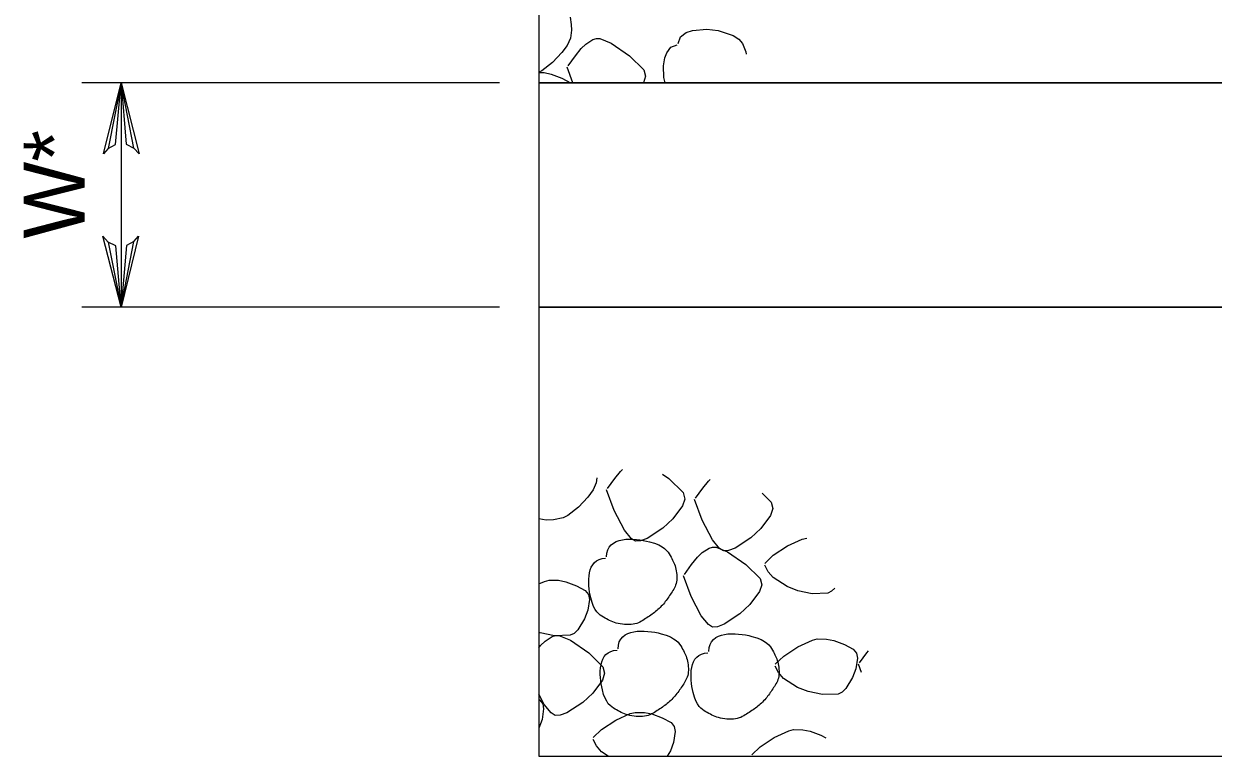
# Model space of a CAD drawing. Extents: x 636462 to 638208, y 299350 to 300538.
# Drawn here: x 637673.2 to 637731.8, y 299723.9 to 299760 of the extents above; entities that cross this region are included whole.
import ezdxf

# ---------------------------------------------------------------- set-up
doc = ezdxf.new("R2010")
doc.units = 0
doc.layers.add('Default', color=7, linetype='Continuous')

msp = doc.modelspace()

# ---------------------------------------------------------------- linework, layer by layer
at = {"layer": 'Default'}
for p, q in [((637700.101, 299760.333), (637700.163, 299759.98)), ((637700.174, 299759.704), (637700.119, 299759.303)), ((637700.163, 299759.98), (637700.174, 299759.704)), ((637705.545, 299759.377), (637705.813, 299759.58)), ((637705.813, 299759.58), (637706.137, 299759.688)), ((637706.137, 299759.688), (637706.833, 299759.743)), ((637706.833, 299759.743), (637707.388, 299759.679)), ((637707.388, 299759.679), (637708.132, 299759.437)), ((637699.967, 299758.951), (637699.704, 299758.594)), ((637700.119, 299759.303), (637699.967, 299758.951)), ((637700.656, 299758.79), (637700.881, 299759.015)), ((637700.881, 299759.015), (637701.227, 299759.243)), ((637701.227, 299759.243), (637701.397, 299759.292)), ((637701.397, 299759.292), (637701.565, 299759.285)), ((637701.565, 299759.285), (637702.13, 299759.057)), ((637702.13, 299759.057), (637703.035, 299758.439)), ((637705.073, 299758.866), (637705.38, 299758.974)), ((637705.423, 299759.041), (637705.545, 299759.377)), ((637708.132, 299759.437), (637708.411, 299759.255)), ((637708.411, 299759.255), (637708.595, 299759.041)), ((637708.595, 299759.041), (637708.752, 299758.638)), ((637699.704, 299758.594), (637699.242, 299758.108)), ((637700.004, 299757.944), (637700.363, 299758.435)), ((637700.363, 299758.435), (637700.656, 299758.79)), ((637703.035, 299758.439), (637703.733, 299757.744)), ((637704.707, 299757.94), (637704.772, 299758.336)), ((637704.772, 299758.336), (637704.864, 299758.589)), ((637704.864, 299758.589), (637705.073, 299758.866)), ((637708.752, 299758.638), (637708.77, 299758.522)), ((637699.242, 299758.108), (637698.716, 299757.7)), ((637700.246, 299757.106), (637699.958, 299757.877)), ((637703.733, 299757.744), (637703.813, 299757.428)), ((637704.721, 299757.362), (637704.707, 299757.94)), ((637698.716, 299757.7), (637698.562, 299757.622)), ((637698.562, 299757.608), (637698.82, 299757.606)), ((637698.82, 299757.606), (637699.179, 299757.532)), ((637699.179, 299757.532), (637699.7, 299757.341)), ((637699.7, 299757.341), (637700.131, 299757.106)), ((637703.813, 299757.428), (637703.712, 299757.106)), ((637704.778, 299757.106), (637704.721, 299757.362)), ((637696.627, 299757.106), (637676.053, 299757.106)), ((637696.627, 299746.05), (637676.053, 299746.05)), ((637702.3, 299737.611), (637702.593, 299737.966)), ((637702.593, 299737.966), (637702.683, 299738.056)), ((637704.649, 299737.837), (637704.97, 299737.616)), ((637701.388, 299737.402), (637701.236, 299737.052)), ((637701.423, 299737.657), (637701.388, 299737.402)), ((637701.939, 299737.121), (637702.3, 299737.611)), ((637704.97, 299737.616), (637705.668, 299736.92)), ((637706.635, 299737.139), (637706.927, 299737.492)), ((637706.927, 299737.492), (637707.006, 299737.572)), ((637700.974, 299736.692), (637700.511, 299736.206)), ((637701.236, 299737.052), (637700.974, 299736.692)), ((637702.275, 299736.034), (637701.895, 299737.054)), ((637705.668, 299736.92), (637705.75, 299736.605)), ((637706.273, 299736.649), (637706.635, 299737.139)), ((637709.555, 299736.89), (637710.002, 299736.448)), ((637700.511, 299736.206), (637699.985, 299735.801)), ((637705.644, 299736.271), (637705.17, 299735.631)), ((637705.75, 299736.605), (637705.644, 299736.271)), ((637706.61, 299735.561), (637706.229, 299736.582)), ((637710.085, 299736.133), (637709.979, 299735.799)), ((637710.002, 299736.448), (637710.085, 299736.133)), ((637698.924, 299735.573), (637698.562, 299735.633)), ((637699.294, 299735.578), (637698.924, 299735.573)), ((637699.755, 299735.684), (637699.294, 299735.578)), ((637699.985, 299735.801), (637699.755, 299735.684)), ((637702.775, 299735.073), (637702.275, 299736.034)), ((637705.17, 299735.631), (637704.675, 299735.175)), ((637707.109, 299734.601), (637706.61, 299735.561)), ((637709.979, 299735.799), (637709.505, 299735.158)), ((637703.129, 299734.647), (637702.775, 299735.073)), ((637704.675, 299735.175), (637703.896, 299734.663)), ((637709.505, 299735.158), (637709.009, 299734.7)), ((637703.325, 299734.532), (637703.129, 299734.647)), ((637703.567, 299734.539), (637703.325, 299734.532)), ((637703.896, 299734.663), (637703.567, 299734.539)), ((637707.464, 299734.175), (637707.109, 299734.601)), ((637709.009, 299734.7), (637708.231, 299734.191)), ((637710.808, 299734.297), (637711.527, 299734.622)), ((637711.527, 299734.622), (637711.762, 299734.682)), ((637711.762, 299734.682), (637711.764, 299734.682)), ((637706.089, 299733.385), (637706.382, 299733.737)), ((637706.382, 299733.737), (637706.61, 299733.965)), ((637706.61, 299733.965), (637706.953, 299734.193)), ((637706.953, 299734.193), (637707.123, 299734.242)), ((637707.123, 299734.242), (637707.291, 299734.235)), ((637707.291, 299734.235), (637707.858, 299734.007)), ((637707.657, 299734.057), (637707.464, 299734.175)), ((637707.902, 299734.064), (637707.657, 299734.057)), ((637707.858, 299734.007), (637708.761, 299733.387)), ((637708.231, 299734.191), (637707.902, 299734.064)), ((637709.696, 299733.438), (637710.11, 299733.836)), ((637710.11, 299733.836), (637710.808, 299734.297)), ((637705.73, 299732.894), (637706.089, 299733.385)), ((637708.761, 299733.387), (637709.459, 299732.694)), ((637709.857, 299733.023), (637709.696, 299733.35)), ((637698.562, 299732.424), (637698.841, 299732.549)), ((637698.841, 299732.549), (637699.076, 299732.609)), ((637699.076, 299732.609), (637699.536, 299732.604)), ((637699.536, 299732.604), (637699.896, 299732.528)), ((637706.064, 299731.807), (637705.686, 299732.828)), ((637709.459, 299732.694), (637709.539, 299732.378)), ((637710.106, 299732.74), (637709.857, 299733.023)), ((637710.788, 299732.293), (637710.106, 299732.74)), ((637699.896, 299732.528), (637700.414, 299732.339)), ((637700.414, 299732.339), (637700.849, 299732.102)), ((637700.849, 299732.102), (637701.006, 299731.906)), ((637709.433, 299732.044), (637708.961, 299731.404)), ((637709.539, 299732.378), (637709.433, 299732.044)), ((637711.317, 299732.091), (637710.788, 299732.293)), ((637712.024, 299731.941), (637711.317, 299732.091)), ((637712.801, 299731.966), (637712.024, 299731.941)), ((637712.983, 299732.061), (637712.801, 299731.966)), ((637713.137, 299732.21), (637712.983, 299732.061)), ((637701.052, 299731.66), (637700.976, 299731.13)), ((637701.006, 299731.906), (637701.052, 299731.66)), ((637706.566, 299730.847), (637706.064, 299731.807)), ((637708.961, 299731.404), (637708.464, 299730.948)), ((637700.976, 299731.13), (637700.817, 299730.711)), ((637706.918, 299730.421), (637706.566, 299730.847)), ((637708.464, 299730.948), (637707.685, 299730.437)), ((637700.817, 299730.711), (637700.483, 299730.172)), ((637707.114, 299730.303), (637706.918, 299730.421)), ((637707.358, 299730.31), (637707.114, 299730.303)), ((637707.685, 299730.437), (637707.358, 299730.31)), ((637698.629, 299730.018), (637698.562, 299730.045)), ((637699.338, 299729.868), (637698.629, 299730.018)), ((637698.868, 299729.61), (637699.214, 299729.84)), ((637699.214, 299729.84), (637699.384, 299729.886)), ((637700.112, 299729.893), (637699.338, 299729.868)), ((637699.384, 299729.886), (637699.552, 299729.879)), ((637699.552, 299729.879), (637700.119, 299729.654)), ((637700.296, 299729.988), (637700.112, 299729.893)), ((637700.119, 299729.654), (637701.022, 299729.034)), ((637700.483, 299730.172), (637700.296, 299729.988)), ((637711.32, 299729.331), (637712.038, 299729.656)), ((637712.038, 299729.656), (637712.275, 299729.714)), ((637712.275, 299729.714), (637712.734, 299729.709)), ((637712.734, 299729.709), (637713.093, 299729.635)), ((637713.093, 299729.635), (637713.614, 299729.446)), ((637698.562, 299729.285), (637698.643, 299729.384)), ((637698.643, 299729.384), (637698.868, 299729.61)), ((637701.022, 299729.034), (637701.72, 299728.339)), ((637710.624, 299728.871), (637711.32, 299729.331)), ((637713.614, 299729.446), (637714.049, 299729.209)), ((637714.049, 299729.209), (637714.203, 299729.013)), ((637714.353, 299728.539), (637714.712, 299729.032)), ((637714.712, 299729.032), (637714.795, 299729.131)), ((637710.207, 299728.472), (637710.624, 299728.871)), ((637714.252, 299728.765), (637714.176, 299728.235)), ((637714.203, 299729.013), (637714.252, 299728.765)), ((637714.461, 299728.064), (637714.309, 299728.472)), ((637701.8, 299728.023), (637701.694, 299727.689)), ((637701.72, 299728.339), (637701.8, 299728.023)), ((637710.368, 299728.058), (637710.207, 299728.382)), ((637710.617, 299727.772), (637710.368, 299728.058)), ((637714.176, 299728.235), (637714.017, 299727.816)), ((637701.694, 299727.689), (637701.222, 299727.049)), ((637711.299, 299727.327), (637710.617, 299727.772)), ((637711.829, 299727.125), (637711.299, 299727.327)), ((637713.68, 299727.277), (637713.496, 299727.095)), ((637714.017, 299727.816), (637713.68, 299727.277)), ((637698.827, 299726.494), (637698.562, 299727)), ((637698.562, 299726.74), (637698.597, 299726.719)), ((637698.597, 299726.719), (637698.753, 299726.524)), ((637701.222, 299727.049), (637700.725, 299726.593)), ((637712.536, 299726.975), (637711.829, 299727.125)), ((637713.312, 299726.998), (637712.536, 299726.975)), ((637713.496, 299727.095), (637713.312, 299726.998)), ((637698.799, 299726.277), (637698.723, 299725.747)), ((637698.753, 299726.524), (637698.799, 299726.277)), ((637699.179, 299726.068), (637698.827, 299726.494)), ((637700.725, 299726.593), (637699.946, 299726.081)), ((637698.723, 299725.747), (637698.564, 299725.328)), ((637699.375, 299725.95), (637699.179, 299726.068)), ((637699.617, 299725.957), (637699.375, 299725.95)), ((637699.946, 299726.081), (637699.617, 299725.957)), ((637701.653, 299725.255), (637702.349, 299725.715)), ((637702.349, 299725.715), (637703.067, 299726.04)), ((637703.067, 299726.04), (637703.302, 299726.1)), ((637703.302, 299726.1), (637703.763, 299726.095)), ((637703.763, 299726.095), (637704.122, 299726.019)), ((637704.122, 299726.019), (637704.64, 299725.83)), ((637704.64, 299725.83), (637705.076, 299725.593)), ((637705.076, 299725.593), (637705.232, 299725.397)), ((637698.564, 299725.328), (637698.562, 299725.321)), ((637701.236, 299724.858), (637701.653, 299725.255)), ((637705.281, 299725.151), (637705.202, 299724.621)), ((637705.232, 299725.397), (637705.281, 299725.151)), ((637710.159, 299724.868), (637710.877, 299725.192)), ((637710.877, 299725.192), (637711.112, 299725.25)), ((637711.112, 299725.25), (637711.573, 299725.245)), ((637711.573, 299725.245), (637711.932, 299725.172)), ((637711.932, 299725.172), (637712.451, 299724.983)), ((637712.451, 299724.983), (637712.695, 299724.851)), ((637701.397, 299724.444), (637701.236, 299724.769)), ((637701.646, 299724.158), (637701.397, 299724.444)), ((637705.202, 299724.621), (637705.043, 299724.202)), ((637709.046, 299724.009), (637709.463, 299724.407)), ((637709.463, 299724.407), (637710.159, 299724.868)), ((637701.978, 299723.939), (637701.646, 299724.158)), ((637705.043, 299724.202), (637704.882, 299723.939))]:
    msp.add_line(p, q, dxfattribs=at)
for points in [[(637698.562, 299779.217), (637698.562, 299757.106), (637836.756, 299757.106), (637836.756, 299779.217), (637698.562, 299779.217)], [(637677.35, 299753.874), (637677.127, 299753.605), (637677.987, 299757.106), (637677.35, 299753.874), (637677.723, 299754.07), (637677.987, 299757.106), (637678.246, 299754.076), (637678.622, 299753.894), (637677.987, 299757.106), (637678.876, 299753.612), (637678.622, 299753.894)], [(637677.987, 299757.106), (637677.987, 299746.05)], [(637698.562, 299757.106), (637698.562, 299746.05), (637836.756, 299746.05), (637836.756, 299757.106), (637698.562, 299757.106)], [(637678.625, 299749.282), (637678.848, 299749.551), (637677.987, 299746.05), (637678.625, 299749.282), (637678.252, 299749.086), (637677.987, 299746.05), (637677.728, 299749.08), (637677.353, 299749.262), (637677.987, 299746.05), (637677.099, 299749.545), (637677.353, 299749.262)], [(637698.562, 299746.05), (637698.562, 299723.939), (637836.756, 299723.939), (637836.756, 299746.05), (637698.562, 299746.05)]]:
    msp.add_lwpolyline(points, dxfattribs=at)
for points in [[(637701.895, 299733.76), (637701.91, 299734.817), (637704.614, 299734.578), (637705.066, 299733.76), (637705.321, 299733.3), (637705.41, 299732.47), (637705.087, 299731.975), (637704.767, 299731.486), (637704.325, 299731.043), (637703.836, 299730.725), (637703.27, 299730.356), (637702.307, 299730.468), (637701.784, 299730.768), (637701.039, 299731.197), (637700.876, 299733.672), (637701.851, 299733.694)], [(637702.464, 299729.232), (637702.477, 299730.289), (637705.182, 299730.05), (637705.635, 299729.232), (637705.891, 299728.771), (637705.982, 299727.94), (637705.658, 299727.445), (637705.338, 299726.955), (637704.896, 299726.512), (637704.408, 299726.194), (637703.84, 299725.825), (637702.877, 299725.939), (637702.353, 299726.24), (637701.608, 299726.669), (637701.445, 299729.144), (637702.42, 299729.165)], [(637706.932, 299729.101), (637706.945, 299730.158), (637709.65, 299729.919), (637710.104, 299729.101), (637710.359, 299728.641), (637710.449, 299727.81), (637710.127, 299727.316), (637709.807, 299726.826), (637709.364, 299726.383), (637708.876, 299726.065), (637708.309, 299725.696), (637707.345, 299725.808), (637706.821, 299726.109), (637706.076, 299726.537), (637705.913, 299729.013), (637706.888, 299729.034)]]:
    msp.add_open_spline(points, degree=3, dxfattribs=at)

# ---------------------------------------------------------------- texts
msp.add_text('W*', height=2.998, rotation=90, dxfattribs=at).set_placement((637676.197, 299749.434))

doc.saveas('drawing.dxf')
